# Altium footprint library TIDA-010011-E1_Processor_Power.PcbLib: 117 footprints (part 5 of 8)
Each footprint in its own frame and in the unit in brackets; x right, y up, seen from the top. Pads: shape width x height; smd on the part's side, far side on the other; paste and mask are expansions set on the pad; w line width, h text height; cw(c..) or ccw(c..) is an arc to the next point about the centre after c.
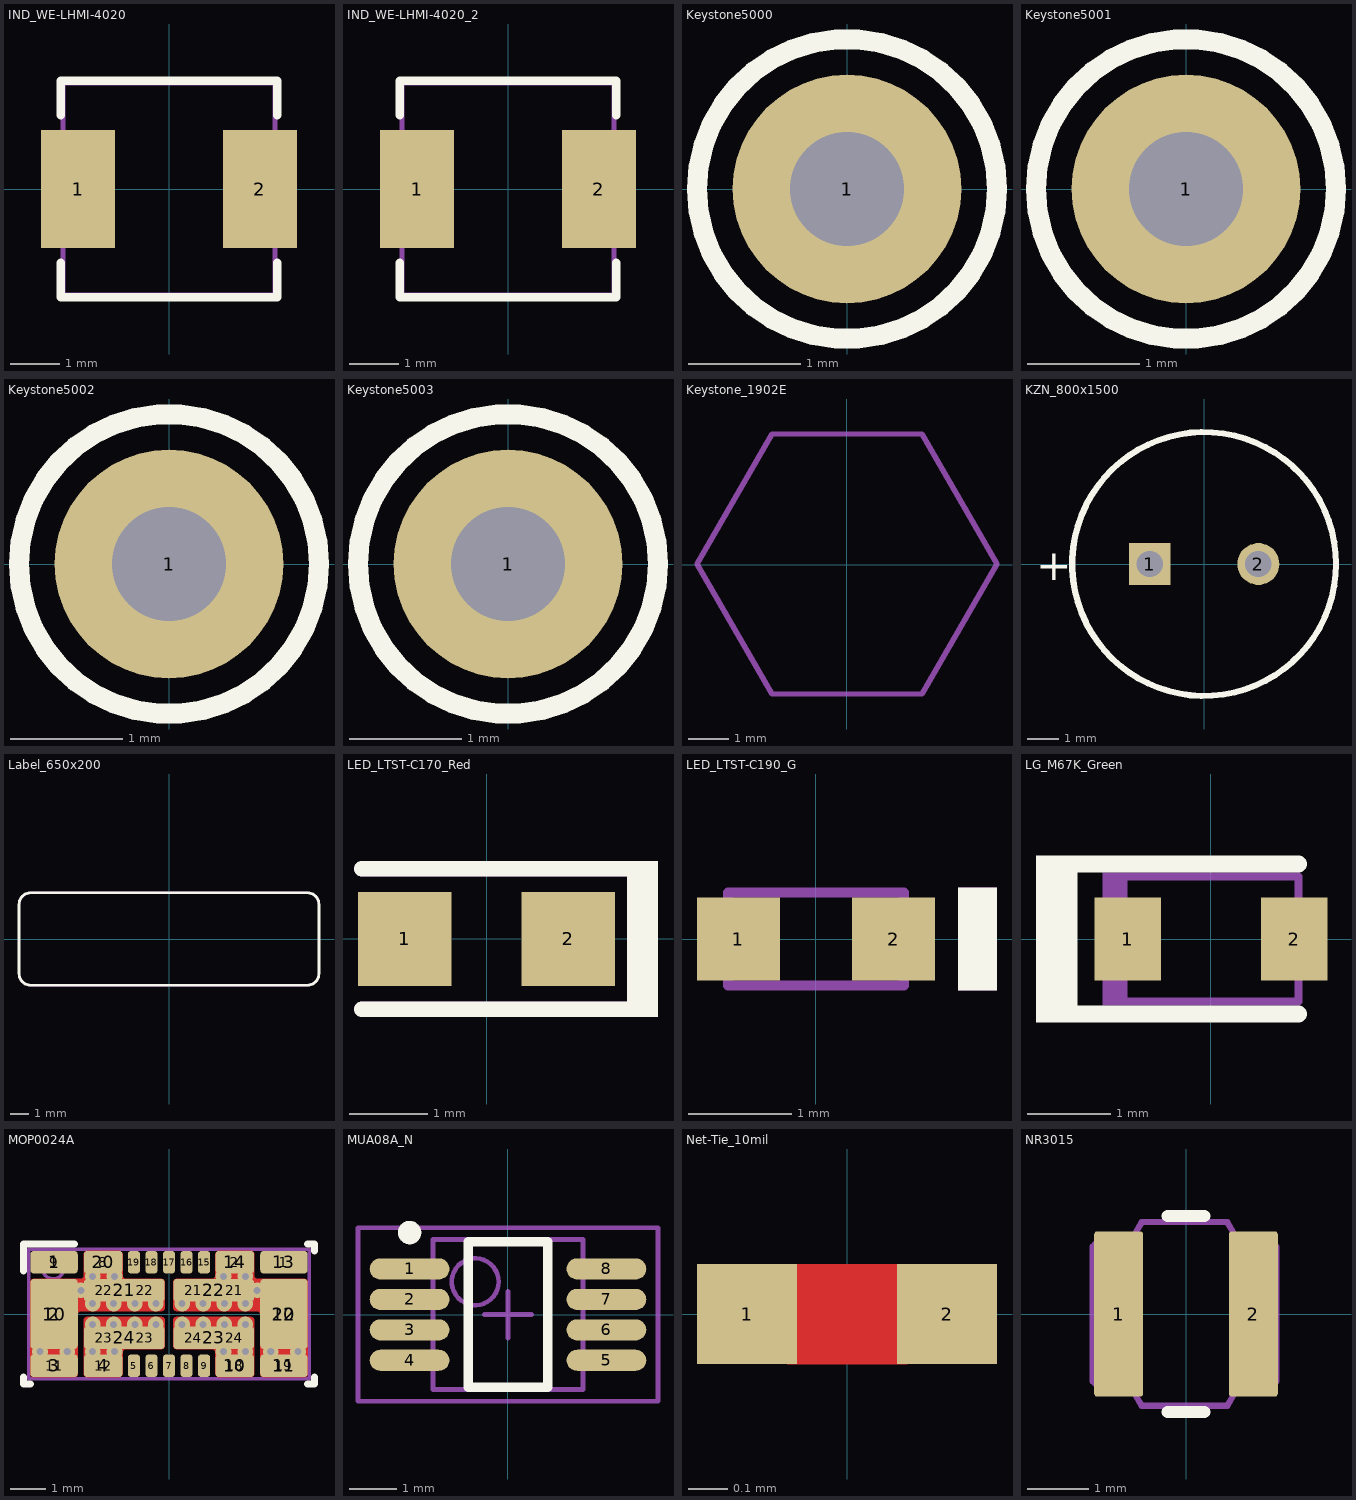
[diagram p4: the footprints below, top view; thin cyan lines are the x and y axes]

## IND_WE-LHMI-4020 [mm] "WERTH"
height 2
pads (2):
  rect 1.5x2.4 smd: 1(-1.85,0) 2(1.85,0)
Top Overlay:
  lines w0.17: -2.2,-1.5 -2.2,-2.2 2.2,-2.2 2.2,-1.5 ; -2.2,1.5 -2.2,2.2 2.2,2.2 2.2,1.5
Mechanical 5:
  lines w0.1: -2.155,-2.155 2.155,-2.155 2.155,2.155 -2.155,2.155 -2.155,-2.155
  text ".Designator" at -1.092,-0.406 h0.51
3D body: height 2, standoff 0, extent -2.154,-2.154 2.154,2.154

## IND_WE-LHMI-4020_2 [mm]
pads (2):
  rect 1.5x2.4 smd: 1(-1.85,0) 2(1.85,0)
Top Overlay:
  lines w0.17: -2.2,-1.5 -2.2,-2.2 2.2,-2.2 2.2,-1.5 ; -2.2,1.5 -2.2,2.2 2.2,2.2 2.2,1.5
Mechanical 5:
  lines w0.1: -2.155,-2.155 2.155,-2.155 2.155,2.155 -2.155,2.155 -2.155,-2.155
  text ".Designator" at -1.8,-0.5 h0.51
3D body: height 2, standoff 0, extent -2.154,-2.154 2.154,2.154

## Keystone5000 [mil] "For Keystone 500x miniature loop terminals"
height 181.1
pads (1):
  round 80 hole 40: 1(0,0)
Top Overlay:
  circle w7: c0,0 r52.5
Mechanical 5:
  circle w3.94: c0,0 r52.5
  text ".Designator" at 56,91 h20
3D body "Keystone_5000.stp": height 181.97, standoff -118.11, extent -49,-49 49.04,49.24

## Keystone5001 [mil] "For Keystone 500x miniature loop terminals"
height 181.1
pads (1):
  round 80 hole 40: 1(0,0)
Top Overlay:
  circle w7: c0,0 r52.5
Mechanical 5:
  circle w3.94: c0,0 r52.5
  text ".Designator" at -103,-14 h20
3D body "Keystone_5001.stp": height 181.97, standoff -118.11, extent -49,-49 49.04,49.24

## Keystone5002 [mil] "For Keystone 500x miniature loop terminals"
height 181.1
pads (1):
  round 80 hole 40: 1(0,0)
Top Overlay:
  circle w7: c0,0 r52.5
Mechanical 5:
  circle w3.94: c0,0 r52.5
  text ".Designator" at -19,101 h20
3D body "Keystone_5002.stp": height 181.97, standoff -118.11, extent -49,-49 49.04,49.23

## Keystone5003 [mil] "For Keystone 500x miniature loop terminals"
height 181.1
pads (1):
  round 80 hole 40: 1(0,0)
Top Overlay:
  circle w7: c0,0 r52.5
Mechanical 5:
  circle w3.94: c0,0 r52.5
  text ".Designator" at 17,-103 h20
3D body "Keystone_5003.stp": height 181.97, standoff -118.11, extent -49,-49 49.04,49.24

## Keystone_1902E [mil] "Hex Standoff, 4-40 threaded, nylon"
height 1000
pads (1):
  round 1 on Mech3: 0(0,0)
Mechanical 5:
  lines w5: -145.29,0.49 -72.56,126.47 72.92,126.47 145.65,0.49 72.92,-125.49 -72.56,-125.49 -145.29,0.49
  text ".Designator" at -60,-20 h20
3D body "Keystone_1902E.stp": height 1001, standoff 1, extent -144.95,-125.98 146,125.98

## KZN_800x1500 [mm] "TH, 2-Leads, Dia 8mm, Pin Spacing 3.5mm"
height 16.5
pads (2):
  rect 1.35x1.35 hole 0.85: 1(-1.75,0)
  round 1.35 hole 0.85: 2(1.75,0)
Top Overlay:
  circle w0.2: c0,0 r4.25
  text "+" at -5.416,-0.527 h1
Mechanical 5:
  circle w0.1: c0,0 r4.25
  text "+" at -3.335,-0.099 h0.51
  text ".Designator" at 0.704,0.409 h0.51
3D body "KZN_800x1500.stp": height 16.51, standoff -3, extent -4.217,-4.243 4.244,4.243

## Label_650x200 [mil] "Thermal Transfer Label"
height 1
pads (1):
  round 1 on Mech13: 0(0,0)
Top Overlay:
  lines w6: -325,-75 ccw(c-300,-75) -300,-100 300,-100 ccw(c300,-75) 325,-75 325,75 ccw(c300,75) 300,100 -300,100 ccw(c-300,75) -325,75 -325,-75
Mechanical 5:
  lines w5: -325,-75 ccw(c-300,-75) -300,-100 300,-100 ccw(c300,-75) 325,-75 325,75 ccw(c300,75) 300,100 -300,100 ccw(c-300,75) -325,75 -325,-75
  text ".Designator" at -60,-20 h20
3D body: height 1, standoff 0, extent -325.02,-100.02 325.02,100.02

## LED_LTST-C170_Red [mm] "LITE-ON"
height 1.1
pads (2):
  rect 1.2x1.2 smd: 1(-1.05,0) 2(1.05,0)
Top Overlay:
  rectangle: 1.8,-1 2.2,1
  lines w0.2: -1.6,-0.9 2.1,-0.9 ; -1.6,0.9 2.1,0.9
Mechanical 5:
  rectangle: 1.8,-1 2.2,1
  lines w0.2: -1.6,-0.9 2.1,-0.9 ; -1.6,0.9 2.1,0.9
  text ".Designator" at 0.554,0.317 h0.51
3D body: height 1.1, standoff 0.5, extent -0.699,-0.624 0.699,0.624
3D body: height 0.5, standoff 0, extent -1.05,-0.675 1.05,0.675

## LED_LTST-C190_G [mm] "Lite-On"
height 0.9
pads (2):
  rect 0.8x0.8 smd: 1(-0.75,0) 2(0.75,0)
Top Overlay:
  rectangle: 1.375,-0.5 1.75,0.5
Mechanical 5:
  rectangle: 1.375,-0.5 1.75,0.5
  lines w0.1: -0.85,-0.45 0.85,-0.45 0.85,0.45 -0.85,0.45 -0.85,-0.45
  text ".Designator" at -0.508,-0.229 h0.51
3D body: height 0.35, standoff 0, extent -0.849,-0.449 0.849,0.449
3D body: height 0.36, standoff 0.35, extent -0.849,-0.449 -0.501,0.449
3D body: height 0.36, standoff 0.35, extent 0.501,-0.449 0.849,0.449
3D body: height 0.9, standoff 0.35, extent -0.499,-0.449 0.499,0.449

## LG_M67K_Green [mm] "SMD, 2-Leads, Body 2x1.4mm, Pitch 2mm"
height 1.4
pads (2):
  rect 0.8x1 smd mask+0: 1(-1,0) 2(1,0)
Top Overlay:
  rectangle: -2.1,-1 -1.6,1
  lines w0.2: -2,-0.9 1.05,-0.9 ; -2,0.9 1.05,0.9
Mechanical 5:
  rectangle: -1.3,-0.8 -1.05,0.8
  lines w0.1: -1.05,-0.75 -1.05,0.75 1.05,0.75 1.05,-0.75 -1.05,-0.75
  text ".Designator" at -0.61,-0.362 h0.51
3D body: height 0.9, standoff 0.6, extent -0.799,-0.149 -0.6,0.15
3D body: height 1.4, standoff 0, extent -1.049,-0.749 1.049,0.749

## MOP0024A [mm] "QFM, 24-Leads, Body 3.6x7.9mm"
height 1.55
pads (42):
  rrect31% 1.35x0.65 smd paste-1 mask-0.05: 1(-3.275,1.475) 3(-3.275,-1.475) 11(3.275,-1.475) 13(3.275,1.475)
  rrect50% 1.17x0.52 on Top Paste: 1(3.275,1.475) 9(-3.275,1.475) 11(-3.275,-1.475) 19(3.275,-1.475)
  rrect15% 1.35x2 smd paste-1 mask-0.05: 2(-3.275,0) 12(3.275,0)
  rrect50% 0.95x0.52 on Top Paste: 2(1.875,1.475) 8(-1.875,1.475) 12(-1.875,-1.475) 18(1.875,-1.475)
  rrect31% 1.1x0.65 smd paste-1 mask-0.05: 4(-1.875,-1.475) 10(1.875,-1.475) 14(1.875,1.475) 20(-1.875,1.475)
  rrect57% 0.35x0.65 smd paste-0.05 mask-0.05: 5(-1,-1.475) 6(-0.5,-1.475) 7(0,-1.475) 8(0.5,-1.475) 9(1,-1.475) 15(1,1.475) 16(0.5,1.475) 17(0,1.475) 18(-0.5,1.475) 19(-1,1.475)
  rrect50% 1.17x1.7 on Top Paste: 10(-3.275,0) 20(3.275,0)
  rrect31% 2.3x0.65 smd paste-1 mask-0.05: 21(-1.275,0.675) 22(1.275,0.675) 23(1.275,-0.675) 24(-1.275,-0.675)
  rrect50% 0.98x0.52 on Top Paste: 21(0.685,0.675) 21(1.865,0.675) 22(-1.865,0.675) 22(-0.685,0.675) 23(-1.865,-0.675) 23(-0.685,-0.675) 24(0.685,-0.675) 24(1.865,-0.675)
via 1.55,-1.075 diameter 0.45 hole 0.2
via -1.55,-1.075 diameter 0.45 hole 0.2
via -0.375,0.3 diameter 0.45 hole 0.2
via -2.175,0.3 diameter 0.45 hole 0.2
via -1.575,0.3 diameter 0.45 hole 0.2
via -0.975,0.3 diameter 0.45 hole 0.2
via -0.375,-0.3 diameter 0.45 hole 0.2
via -2.175,-0.3 diameter 0.45 hole 0.2
via -1.575,-0.3 diameter 0.45 hole 0.2
via -0.975,-0.3 diameter 0.45 hole 0.2
via -1.55,1.075 diameter 0.45 hole 0.2
via 1.575,0.3 diameter 0.45 hole 0.2
via 0.375,0.3 diameter 0.45 hole 0.2
via 0.975,0.3 diameter 0.45 hole 0.2
via 2.175,0.3 diameter 0.45 hole 0.2
via 1.575,-0.3 diameter 0.45 hole 0.2
via 0.375,-0.3 diameter 0.45 hole 0.2
via 0.975,-0.3 diameter 0.45 hole 0.2
via 2.175,-0.3 diameter 0.45 hole 0.2
via 1.55,1.075 diameter 0.45 hole 0.2
via -2.175,-1.075 diameter 0.45 hole 0.2
via 2.175,-1.075 diameter 0.45 hole 0.2
via 2.175,1.075 diameter 0.45 hole 0.2
via -2.175,1.075 diameter 0.45 hole 0.2
via 2.512,0.675 diameter 0.45 hole 0.2
via -2.512,0.675 diameter 0.45 hole 0.2
via 2.9,-1.075 diameter 0.45 hole 0.2
via 3.675,-1.075 diameter 0.45 hole 0.2
via -3.675,-1.075 diameter 0.45 hole 0.2
via -2.9,-1.075 diameter 0.45 hole 0.2
Top Layer:
  region: -3.85,1 -3.87,1 -3.907,0.985 -3.935,0.957 -3.95,0.92 -3.95,0.9 -3.95,-1.7 -3.95,-1.72 -3.935,-1.757 -3.907,-1.785 -3.87,-1.8 -3.85,-1.8 -2.7,-1.8 -2.68,-1.8 -2.643,-1.785 -2.615,-1.757 -2.6,-1.72 -2.6,-1.7 -2.6,-0.025 -2.598,-0.005 -2.583,0.031 -2.556,0.058 -2.52,0.073 -2.5,0.075 -0.225,0.075 -0.205,0.075 -0.168,0.09 -0.14,0.118 -0.125,0.155 -0.125,0.175 -0.125,0.9 -0.125,0.92 -0.14,0.957 -0.168,0.985 -0.205,1 -0.225,1 -1.225,1 -1.245,1.002 -1.281,1.017 -1.308,1.044 -1.323,1.08 -1.325,1.1 -1.325,1.7 -1.325,1.72 -1.34,1.757 -1.368,1.785 -1.405,1.8 -1.425,1.8 -2.325,1.8 -2.345,1.8 -2.382,1.785 -2.41,1.757 -2.425,1.72 -2.425,1.7 -2.425,1.1 -2.427,1.08 -2.442,1.044 -2.469,1.017 -2.505,1.002 -2.525,1
  region: 3.85,1 3.87,1 3.907,0.985 3.935,0.957 3.95,0.92 3.95,0.9 3.95,-1.7 3.95,-1.72 3.935,-1.757 3.907,-1.785 3.87,-1.8 3.85,-1.8 2.7,-1.8 2.68,-1.8 2.643,-1.785 2.615,-1.757 2.6,-1.72 2.6,-1.7 2.6,-0.025 2.598,-0.005 2.583,0.031 2.556,0.058 2.52,0.073 2.5,0.075 0.225,0.075 0.205,0.075 0.168,0.09 0.14,0.118 0.125,0.155 0.125,0.175 0.125,0.9 0.125,0.92 0.14,0.957 0.168,0.985 0.205,1 0.225,1 1.225,1 1.245,1.002 1.281,1.017 1.308,1.044 1.323,1.08 1.325,1.1 1.325,1.7 1.325,1.72 1.34,1.757 1.368,1.785 1.405,1.8 1.425,1.8 2.325,1.8 2.345,1.8 2.382,1.785 2.41,1.757 2.425,1.72 2.425,1.7 2.425,1.1 2.427,1.08 2.442,1.044 2.469,1.017 2.505,1.002 2.525,1
  region: -2.325,-1.8 -2.345,-1.8 -2.382,-1.785 -2.41,-1.757 -2.425,-1.72 -2.425,-1.7 -2.425,-0.175 -2.425,-0.155 -2.41,-0.118 -2.382,-0.09 -2.345,-0.075 -2.325,-0.075 -0.225,-0.075 -0.205,-0.075 -0.168,-0.09 -0.14,-0.118 -0.125,-0.155 -0.125,-0.175 -0.125,-0.9 -0.125,-0.92 -0.14,-0.957 -0.168,-0.985 -0.205,-1 -0.225,-1 -1.225,-1 -1.245,-1.002 -1.281,-1.017 -1.308,-1.044 -1.323,-1.08 -1.325,-1.1 -1.325,-1.7 -1.325,-1.72 -1.34,-1.757 -1.368,-1.785 -1.405,-1.8 -1.425,-1.8
  region: 2.325,-1.8 2.345,-1.8 2.382,-1.785 2.41,-1.757 2.425,-1.72 2.425,-1.7 2.425,-0.175 2.425,-0.155 2.41,-0.118 2.382,-0.09 2.345,-0.075 2.325,-0.075 0.225,-0.075 0.205,-0.075 0.168,-0.09 0.14,-0.118 0.125,-0.155 0.125,-0.175 0.125,-0.9 0.125,-0.92 0.14,-0.957 0.168,-0.985 0.205,-1 0.225,-1 1.225,-1 1.245,-1.002 1.281,-1.017 1.308,-1.044 1.323,-1.08 1.325,-1.1 1.325,-1.7 1.325,-1.72 1.34,-1.757 1.368,-1.785 1.405,-1.8 1.425,-1.8
Top Overlay:
  lines w0.2: -4.15,-1.8 -4.15,-2 -3.95,-2 ; -4.15,1.225 -4.15,2 -2.7,2 ; 3.95,-2 4.15,-2 4.15,-1.8 ; 3.95,2 4.15,2 4.15,1.8
Mechanical 5:
  circle w0.1: c-3.3,1.3 r0.3
  lines w0.1: -4,-1.85 -4,1.85 4,1.85 4,-1.85 -4,-1.85
  text ".Designator" at 1.268,-4.946 h0.51
3D body: height 1.55, standoff 0.5, extent -1.5,-1.7 1.5,1.7
3D body: height 1.55, standoff 0.5, extent -3.9,-1.7 -2,1.7
3D body: height 1.55, standoff 0.5, extent 2,-1.7 3.9,1.7
3D body: height 0.5, standoff 0, extent -4,-1.85 4,1.85
3D body: height 1.55, standoff 1.55, extent 3.001,1.001 3.599,1.599

## MUA08A_N [mm] "TSOP, 8-Leads, Body 3x3mm, Pitch 0.65mm, IPC Medium Density"
height 1.09
pads (8):
  oval 1.7x0.45 smd: 1(-2.1,0.975) 2(-2.1,0.325) 3(-2.1,-0.325) 4(-2.1,-0.975) 5(2.1,-0.975) 6(2.1,-0.325) 7(2.1,0.325) 8(2.1,0.975)
Top Overlay:
  circle w0.25: c-2.1,1.75 r0.125
  lines w0.2: -0.85,-1.55 0.85,-1.55 0.85,1.55 -0.85,1.55 -0.85,-1.55
Mechanical 5:
  text ".Designator" at -0.457,-0.286 h0.51
Mechanical 13:
  circle w0.1: c-0.7,0.7 r0.5
  lines w0.1: -1.6,-1.6 1.6,-1.6 1.6,1.6 -1.6,1.6 -1.6,-1.6
Mechanical 15:
  lines w0.1: -0.5,0 0.5,0 ; 0,-0.5 0,0.5 ; -3.2,-1.85 3.2,-1.85 3.2,1.85 -3.2,1.85 -3.2,-1.85
3D body: height 1.09, standoff 0, extent -1.6,-1.6 1.6,1.6

## Net-Tie_10mil [mil] "10mil net tie, no solder mask opening, no solder paste"
height 1299.21
pads (2):
  rect 10x10 smd paste-5 mask-5: 1(-10,0) 2(10,0)
Top Layer:
  region: -6,5 6,5 6,-5 -6,-5

## NR3015 [mm] "SMD, 2-Leads, Body 3x3mm"
height 1.5
pads (2):
  rrect12% 0.8x2.7 smd: 1(-1.1,0) 2(1.1,0)
Top Overlay:
  lines w0.2: -0.3,-1.6 0.3,-1.6 ; -0.3,1.6 0.3,1.6
Mechanical 5:
  lines w0.1: -1.324,-1.199 -1.324,1.201 ; -1.324,-1.199 -1.424,-1.199 -1.473,-1.151 -1.524,-1.099 -1.524,-0.512 -1.524,0.514 -1.524,1.101 -1.473,1.153 -1.424,1.201 -1.324,1.201 ; -1.324,-1.199 -0.898,-1.199 -0.724,-1.499 0.676,-1.499 0.849,-1.199 1.276,-1.199 ; -1.324,1.201 -0.898,1.201 -0.724,1.501 0.676,1.501 0.849,1.201 1.276,1.201 ; 1.276,-1.199 1.276,1.201 ; 1.276,-1.199 1.376,-1.199 1.424,-1.151 1.476,-1.099 1.476,-0.512 1.476,0.514 1.476,1.101 1.424,1.153 1.376,1.201 1.276,1.201
  text ".Designator" at -0.197,-0.257 h0.51
3D body "NR3015.stp": height 1.5, standoff 0.01, extent -1.5,-1.5 1.5,1.5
